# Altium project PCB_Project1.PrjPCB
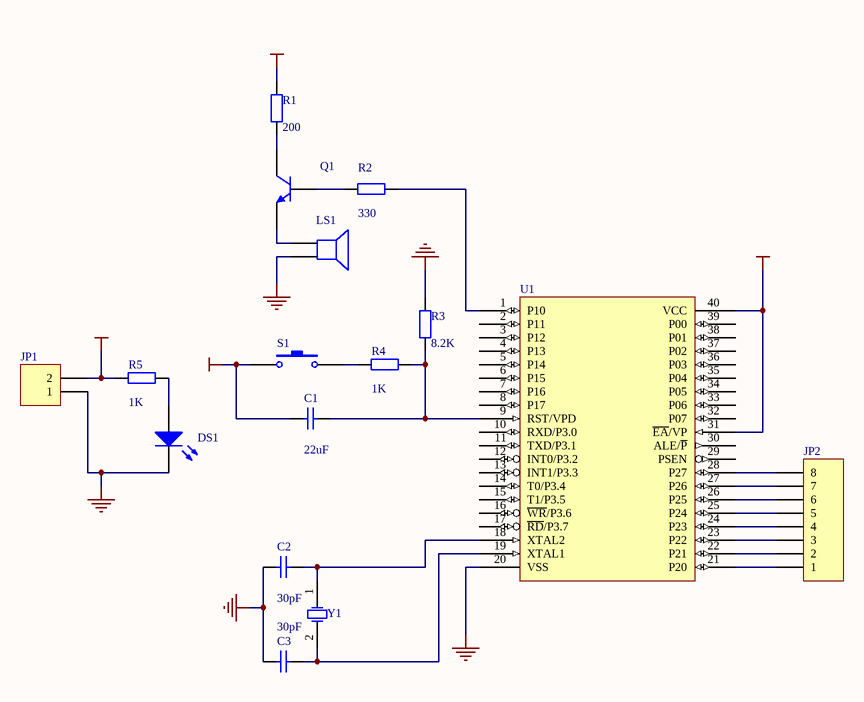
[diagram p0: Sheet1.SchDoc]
1 sheet, 16 parts. Net scope: global (net labels, ports and power ports of the same name join across sheets).
Board file: PCB1.PcbDoc

## Sheet Sheet1.SchDoc
size A4

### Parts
C1  value 22uF  [RAD-0.1]  (hidden comment: Cap)
C2  value 30pF  [RAD-0.1]  (hidden comment: Cap)
C3  value 30pF  [RAD-0.1]  (hidden comment: Cap)
DS1  LED0  [LED-0]  (value not drawn)
JP1  Header 2  [HDR1X2]  (value not drawn)
JP2  Header 8H  [DIP8]  (value not drawn)
LS1  Speaker  [PIN2]  (value not drawn)
Q1  2N3904  [BCY-W3/E4]  (value not drawn)
R1  value 200  [AXIAL-0.4]  (hidden comment: Res2)
R2  value 330  [AXIAL-0.4]  (hidden comment: Res2)
R3  value 8.2K  [AXIAL-0.4]  (hidden comment: Res2)
R4  value 1K  [AXIAL-0.4]  (hidden comment: Res2)
R5  value 1K  [AXIAL-0.4]  (hidden comment: Res2)
S1  SW-PB  [SW0.2]  (value not drawn)
U1  89S51  [DIP40]  (value not drawn)
Y1  XTAL  [BCY-W2/D3.1]  (value not drawn)

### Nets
GND: C2.1 C3.1 DS1.2(K) JP1.1 LS1.2 R3.2 U1.20(VSS)
VCC: C1.1 JP1.2 R1.2 R5.1 S1.1 U1.31(~{EA}/VP) U1.40(VCC)
NetC1_2: C1.2 R3.1 R4.1 U1.9(RST/VPD)
NetC2_2: C2.2 U1.18(XTAL2) Y1.1(OSC1)
NetC3_2: C3.2 U1.19(XTAL1) Y1.2(OSC2)
NetDS1_1: DS1.1(A) R5.2
NetJP2_1: JP2.1 U1.21(P20)
NetJP2_2: JP2.2 U1.22(P21)
NetJP2_3: JP2.3 U1.23(P22)
NetJP2_4: JP2.4 U1.24(P23)
NetJP2_5: JP2.5 U1.25(P24)
NetJP2_6: JP2.6 U1.26(P25)
NetJP2_7: JP2.7 U1.27(P26)
NetJP2_8: JP2.8 U1.28(P27)
NetLS1_1: LS1.1 Q1.1(E)
NetQ1_2: Q1.2(B) R2.1
NetQ1_3: Q1.3(C) R1.1
NetR2_2: R2.2 U1.1(P10)
NetR4_2: R4.2 S1.2

Not connected (* = marked no-connect by the designer): U1 2(P11) 3(P12) 4(P13) 5(P14) 6(P15) 7(P16) 8(P17) 10(RXD/P3.0) 11(TXD/P3.1) 12(INT0/P3.2) 13(INT1/P3.3) 14(T0/P3.4) 15(T1/P3.5) 16(~{WR}/P3.6) 17(~{RD}/P3.7) 29(PSEN) 30(ALE/~{P}) 32(P07) 33(P06) 34(P05) 35(P04) 36(P03) 37(P02) 38(P01) 39(P00)

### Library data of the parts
C1-C3 = Cap: Capacitor
DS1 = LED0: Typical INFRARED GaAs LED
JP1 = Header 2: Header, 2-Pin
JP2 = Header 8H: Header, 8-Pin, Right Angle
LS1 = Speaker: Loudspeaker
Q1 = 2N3904: NPN General Purpose Amplifier; Revision 1: 11-Jul-2000: SIM Model Added.; Revision 2: 17-Jul-2002: Re-released for DXP Platform.; Revision 3: 15-Jan-2003: PCB Footprint 'BCY-W3/D4.7' replaced; Code - JEDEC: TO-92A
R1-R5 = Res2: Resistor
S1 = SW-PB: Switch
Y1 = XTAL: Crystal Oscillator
